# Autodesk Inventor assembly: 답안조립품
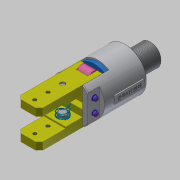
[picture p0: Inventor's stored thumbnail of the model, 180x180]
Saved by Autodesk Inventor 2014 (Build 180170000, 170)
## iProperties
Created: 2019-02
Part Number: 답안조립품
Document SubType Name: Assembly
Designer: 603-14
Author: 603-14
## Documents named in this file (11)
- C:\Users\603-14\Desktop\490208V1005\답안조립품.iam
- C:\Users\603-14\Desktop\490208V1005\본체.ipt
- C:\Users\603-14\Desktop\490208V1005\O-링.ipt
- C:\Users\603-14\Desktop\490208V1005\피스톤.ipt
- C:\Users\603-14\Desktop\490208V1005\핑거.ipt
- C:\Users\603-14\Desktop\490208V1005\평행핀 6x28.ipt
- C:\Users\603-14\Desktop\490208V1005\부시.ipt
- C:\Users\603-14\Desktop\490208V1005\핀.ipt
- C:\Users\603-14\Desktop\490208V1005\E-링.ipt
- C:\Users\603-14\Desktop\490208V1005\가이드핀.ipt
- C:\Users\603-14\Desktop\490208V1005\스프링.ipt
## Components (13 placed, 6 different names)
1. O-링:1
2. O-링:2
3. 피스톤:1
4. 핑거:1 — 플러쉬:2
5. 핑거:2 — 플러쉬:1
6. 핀:1
7. 핀:2
8. E-링:1
9. E-링:2
10. E-링:3
11. E-링:4
12. 가이드핀:1
13. 가이드핀:2
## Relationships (2: Flush 2)
- 플러쉬:1 [Flush]: 핑거:2
- 플러쉬:2 [Flush]: 핑거:1
